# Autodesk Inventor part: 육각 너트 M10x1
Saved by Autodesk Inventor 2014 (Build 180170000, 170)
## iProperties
Created: 2024-08
Part Number: 육각 너트 M10x1
Material: 일반
Document SubType Name: Modeling
Designer: dg
Density: 1 g/cm^3
Appearance: 기본값
Author: dg
Author: jhkim
Description: 6각 너트 및 6각 가는 너트
Creation Date: 2024-08-09
Sending System: Autodesk Inventor 2025
Preprocessor: ST-DEVELOPER v20
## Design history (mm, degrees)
node "육각 너트 M10x11"
body "Solid1"
node "기준1"
